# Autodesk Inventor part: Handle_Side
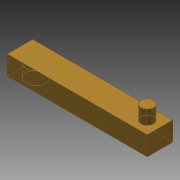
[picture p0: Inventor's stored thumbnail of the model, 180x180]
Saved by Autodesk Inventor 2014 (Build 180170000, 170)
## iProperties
Created: 2014-03
Part Number: Handle_Side
Material: Brass, Soft Yellow
Document SubType Name: Modeling
Designer: Beast
Density: 8.47 g/cm^3
Appearance: Brass - Satin
Author: Beast
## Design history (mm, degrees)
sketch "Sketch1"
  geometry: L1 (0, 0)-(69.85, 0); L2 (69.85, 0)-(69.85, 12.7); L3 (69.85, 12.7)-(0, 12.7); L4 (0, 12.7)-(0, 0)
  constraints: 8 end point, 2 parallel, 1 horizontal, 1 perpendicular
  dimensions: "d0" = 69.85 distance of L3.end L2.end; "d1" = 12.7 distance of L2.end L1.end
extrude "Extrusion1" new body sketch "Sketch1" distance "d2" = 9.525; taper "d3" = 0 deg
hole "Hole2" diameter "d24" = 9.525; stored, may be unused: countersink angle "d28" = 82 deg, drill point angle "d30" = 0 deg; dims "d22" = 7.9375, "d23" = 6.35, "d25" = 19.05, "d26" = 9.525, "d27" = 6.35, "d29" = 6.35
sketch "Sketch4"
  geometry: L1 (0, -12.7)-(0, 0) reference; C1 r 3.175 at (-6.35, -6.35)
  constraints: 1 centre point
  dimensions: "d31" = 6.35 diameter of C1; "d32" = 6.35 distance from line of L1 C1.centre
extrude "Extrusion3" join sketch "Sketch4" distance "d33" = 6.985; taper "d34" = 0 deg
body "Solid1"
